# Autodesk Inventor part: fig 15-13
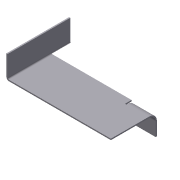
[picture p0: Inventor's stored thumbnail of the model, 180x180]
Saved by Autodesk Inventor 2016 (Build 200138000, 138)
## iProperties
Shininess: 77.0
Angle Display Precision: 2
Document Length Units: 11269
Document Angle Units: 11279
Document Time Units: 11290
Document Mass Units: 11283
Document Length Units Precision: 3
Document Angle Units Precision: 2
Created: 2002-04
Part Number: fig 15-13
Material: Aluminum-6061
Document SubType Name: Sheet Metal
Density: 1 g/cm^3
Sheet Metal Rule: Default
Appearance: Aluminum - Flat-1
Density: 0.0
Volumn: 0.0
Area: 0.0
PropertySet Name: Model Information
Control State: 0
Master: False
Checked Out: False
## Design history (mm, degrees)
node "Face1"
  sketch "Sketch1"
    geometry: L1 (-49.559, 19.574)-(-49.559, -30.426); L2 (-49.559, -30.426)-(50.441, -30.426); L3 (50.441, -30.426)-(50.441, 19.574); L4 (50.441, 19.574)-(32.941, 19.574); L5 (32.941, 19.574)-(32.941, 4.574); L6 (32.941, 4.574)-(-32.059, 4.574); L7 (-32.059, 4.574)-(-32.059, 19.574); L8 (-32.059, 19.574)-(-49.559, 19.574)
    constraints: 16 end point, 6 parallel, 2 equal length, 1 perpendicular, 1 vertical
    dimensions: "d0" = 100 distance of L1.end L2.end; "d1" = 65 distance of L5.end L6.end; "d2" = 15 distance of L6.end L7.end; "d3" = 50 distance of L1.start L1.end
sketch "Sketch2"
  geometry: L1 (100, 0)-(0, 0) reference; L2 (17.5, 50)-(17.5, 35) reference; L3 (82.5, 50)-(82.5, 0)
  constraints: 2 end point, 1 parallel, 1 point on line
sketch "Sketch3"
  geometry: L1 (81.369, -50)-(0, -50) reference; L2 (17.5, 0)-(17.5, -50)
  constraints: 2 end point, 1 perpendicular, 1 point on line
feature "Fold2" sketch "Sketch3" dims "d8" = 1 (= BendRadius), "d9" = 90 deg, "d10" = 1 (= BendRadius), "d14" = 1 (= BendReliefWidth), "d15" = 0.5 (= BendReliefDepth), "d16" = 2 (= MinimumRemnant), "SeamGap" = 0.01, "Thickness" = 1
sketch "Sketch4"
  geometry: L1 (17.5, 0)-(17.5, -50) reference; L2 (-63.869, -15)-(0, -15) reference; L3 (0, -15)-(17.5, -15)
  constraints: 2 end point, 1 collinear, 1 point on line
feature "Fold3" sketch "Sketch4" dims "d11" = 1 (= BendRadius), "d12" = 90 deg, "d13" = 5, "d17" = 1 (= BendReliefWidth), "d18" = 1, "d19" = 2 (= MinimumRemnant), "SeamGap" = 0.01, "Thickness" = 1
body "Solid1"
face "Plate1" dims "Thickness" = 1
other parameters: "BendRadius" = 1 (= Thickness), "BendReliefWidth" = 1 (= Thickness), "BendReliefDepth" = 0.5 (= 0.5 x Thickness), "CornerReliefSize" = 4 (= 4 x Thickness), "MinimumRemnant" = 2 (= 2 x Thickness), "TransitionRadius" = 1 (= BendRadius), "d4" = 1 (= BendRadius), "JacobiRadiusSize" = 1 (= Thickness), "GapSize" = 1 (= Thickness)
